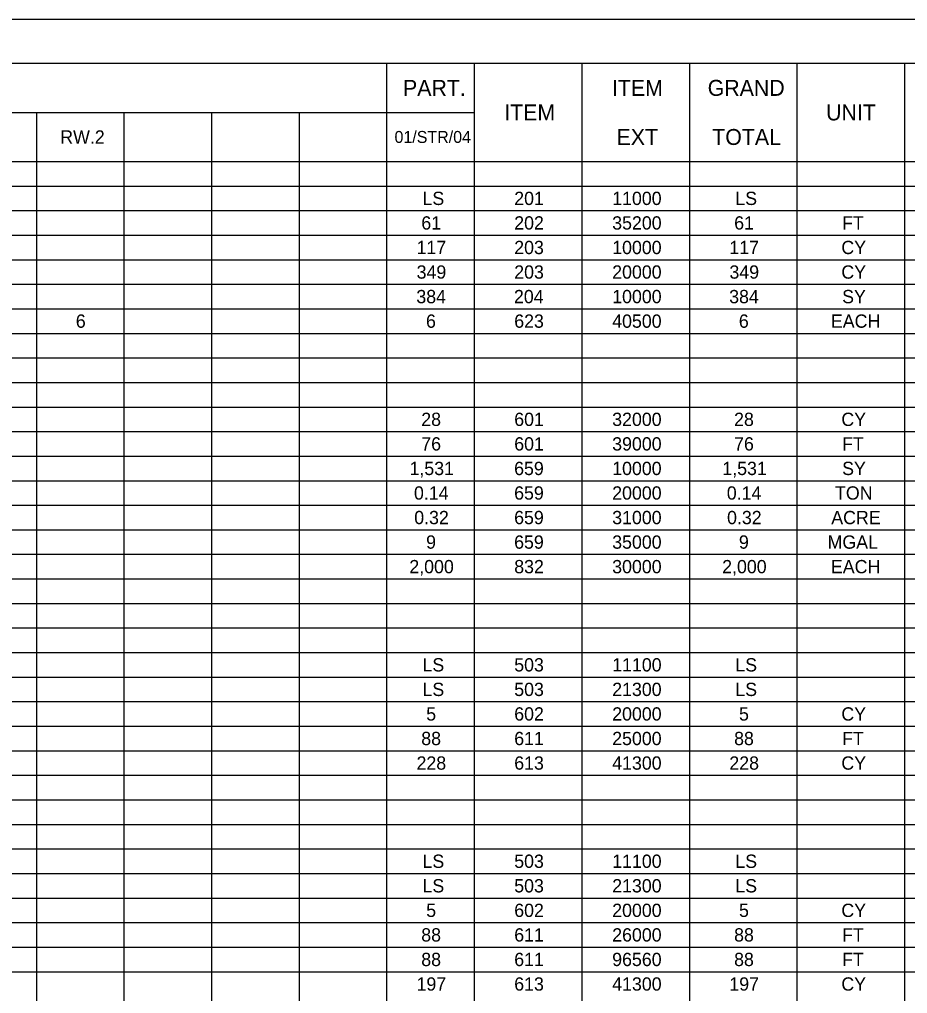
# Model space of a CAD drawing. Extents: x 0 to 44.3, y 0 to 22.
# Drawn here: x 10.6 to 20.73, y 10.89 to 22 of the extents above; entities that cross this region are included whole.
import ezdxf

# ---------------------------------------------------------------- set-up
doc = ezdxf.new("R2010")
doc.units = 0
for name, color, linetype in [('SH_Border', 7, 'Continuous'), ('SH_Cut_Line', 7, 'Continuous'), ('SH_Text', 7, 'Continuous')]:
    doc.layers.add(name, color=color, linetype=linetype)

msp = doc.modelspace()

# ---------------------------------------------------------------- linework, layer by layer
at = {"layer": 'SH_Border'}
msp.add_lwpolyline([(1.5, 21.5), (33.5, 21.5), (33.5, 0.5), (1.5, 0.5)], close=True, dxfattribs=at)
at = {"layer": 'SH_Cut_Line'}
msp.add_lwpolyline([(0, 0), (34, 0), (34, 22), (0, 22)], close=True, dxfattribs=at)
at = {"layer": 'SH_Text'}
for p, q in [((1.5, 21.5), (32, 21.5)), ((14.786, 21.5), (14.786, 0.5)), ((15.785, 21.5), (15.785, 0.5)), ((17.012, 21.5), (17.012, 0.5)), ((18.239, 21.5), (18.239, 0.5)), ((19.466, 21.5), (19.466, 0.5)), ((20.693, 21.5), (20.693, 0.5)), ((1.5, 20.94), (15.785, 20.94)), ((10.794, 20.94), (10.794, 0.5)), ((11.792, 20.94), (11.792, 0.5)), ((12.79, 20.94), (12.79, 0.5)), ((13.788, 20.94), (13.788, 0.5)), ((1.5, 20.38), (32, 20.38)), ((1.5, 20.1), (32, 20.1)), ((1.5, 19.82), (32, 19.82)), ((1.5, 19.54), (32, 19.54)), ((1.5, 19.26), (32, 19.26)), ((1.5, 18.98), (32, 18.98)), ((1.5, 18.7), (32, 18.7)), ((1.5, 18.42), (32, 18.42)), ((1.5, 18.14), (32, 18.14)), ((1.5, 17.86), (32, 17.86)), ((1.5, 17.58), (32, 17.58)), ((1.5, 17.3), (32, 17.3)), ((1.5, 17.02), (32, 17.02)), ((1.5, 16.74), (32, 16.74)), ((1.5, 16.46), (32, 16.46)), ((1.5, 16.18), (32, 16.18)), ((1.5, 15.9), (32, 15.9)), ((1.5, 15.62), (32, 15.62)), ((1.5, 15.34), (32, 15.34)), ((1.5, 15.06), (32, 15.06)), ((1.5, 14.78), (32, 14.78)), ((1.5, 14.5), (32, 14.5)), ((1.5, 14.22), (32, 14.22)), ((1.5, 13.94), (32, 13.94)), ((1.5, 13.66), (32, 13.66)), ((1.5, 13.38), (32, 13.38)), ((1.5, 13.1), (32, 13.1)), ((1.5, 12.82), (32, 12.82)), ((1.5, 12.54), (32, 12.54)), ((1.5, 12.26), (32, 12.26)), ((1.5, 11.98), (32, 11.98)), ((1.5, 11.7), (32, 11.7)), ((1.5, 11.42), (32, 11.42)), ((1.5, 11.14), (32, 11.14))]:
    msp.add_line(p, q, dxfattribs=at)

# ---------------------------------------------------------------- texts
for s, height, p in [('PART.', 0.1818, (14.974, 21.129)), ('ITEM', 0.1818, (17.356, 21.129)), ('GRAND', 0.1818, (18.448, 21.129)), ('ITEM', 0.1818, (16.128, 20.849)), ('UNIT', 0.1818, (19.798, 20.849)), ('RW.2', 0.1515, (11.066, 20.584)), ('01/STR/04', 0.1364, (14.877, 20.592)), ('EXT', 0.1818, (17.409, 20.569)), ('TOTAL', 0.1818, (18.5, 20.569)), ('LS', 0.1515, (15.196, 19.884)), ('201', 0.1515, (16.242, 19.884)), ('11000', 0.1515, (17.359, 19.884)), ('LS', 0.1515, (18.763, 19.884)), ('61', 0.1515, (15.183, 19.604)), ('202', 0.1515, (16.242, 19.604)), ('35200', 0.1515, (17.359, 19.604)), ('61', 0.1515, (18.75, 19.604)), ('FT', 0.1515, (19.98, 19.604)), ('117', 0.1515, (15.128, 19.324)), ('203', 0.1515, (16.242, 19.324)), ('10000', 0.1515, (17.359, 19.324)), ('117', 0.1515, (18.695, 19.324)), ('CY', 0.1515, (19.972, 19.324)), ('349', 0.1515, (15.129, 19.044)), ('203', 0.1515, (16.242, 19.044)), ('20000', 0.1515, (17.359, 19.044)), ('349', 0.1515, (18.696, 19.044)), ('CY', 0.1515, (19.972, 19.044)), ('384', 0.1515, (15.126, 18.764)), ('204', 0.1515, (16.239, 18.764)), ('10000', 0.1515, (17.359, 18.764)), ('384', 0.1515, (18.693, 18.764)), ('SY', 0.1515, (19.981, 18.764)), ('6', 0.152, (11.243, 18.484)), ('6', 0.152, (15.236, 18.484)), ('623', 0.1515, (16.242, 18.484)), ('40500', 0.1515, (17.359, 18.484)), ('6', 0.152, (18.803, 18.484)), ('EACH', 0.1515, (19.853, 18.484)), ('28', 0.1515, (15.182, 17.364)), ('601', 0.1515, (16.242, 17.364)), ('32000', 0.1515, (17.359, 17.364)), ('28', 0.1515, (18.749, 17.364)), ('CY', 0.1515, (19.972, 17.364)), ('76', 0.1515, (15.182, 17.084)), ('601', 0.1515, (16.242, 17.084)), ('39000', 0.1515, (17.359, 17.084)), ('76', 0.1515, (18.749, 17.084)), ('FT', 0.1515, (19.98, 17.084)), ('1,531', 0.1515, (15.048, 16.804)), ('659', 0.1515, (16.241, 16.804)), ('10000', 0.1515, (17.359, 16.804)), ('1,531', 0.1515, (18.615, 16.804)), ('SY', 0.1515, (19.981, 16.804)), ('0.14', 0.1515, (15.099, 16.524)), ('659', 0.1515, (16.241, 16.524)), ('20000', 0.1515, (17.359, 16.524)), ('0.14', 0.1515, (18.666, 16.524)), ('TON', 0.1515, (19.9, 16.524)), ('0.32', 0.1515, (15.102, 16.244)), ('659', 0.1515, (16.241, 16.244)), ('31000', 0.1515, (17.359, 16.244)), ('0.32', 0.1515, (18.669, 16.244)), ('ACRE', 0.1515, (19.857, 16.244)), ('9', 0.152, (15.237, 15.964)), ('659', 0.1515, (16.241, 15.964)), ('35000', 0.1515, (17.359, 15.964)), ('9', 0.152, (18.804, 15.964)), ('MGAL', 0.1515, (19.815, 15.964)), ('2,000', 0.1515, (15.046, 15.684)), ('832', 0.1515, (16.242, 15.684)), ('30000', 0.1515, (17.359, 15.684)), ('2,000', 0.1515, (18.613, 15.684)), ('EACH', 0.1515, (19.853, 15.684)), ('LS', 0.1515, (15.196, 14.564)), ('503', 0.1515, (16.242, 14.564)), ('11100', 0.1515, (17.359, 14.564)), ('LS', 0.1515, (18.763, 14.564)), ('LS', 0.1515, (15.196, 14.284)), ('503', 0.1515, (16.242, 14.284)), ('21300', 0.1515, (17.359, 14.284)), ('LS', 0.1515, (18.763, 14.284)), ('5', 0.152, (15.238, 14.004)), ('602', 0.1515, (16.242, 14.004)), ('20000', 0.1515, (17.359, 14.004)), ('5', 0.152, (18.805, 14.004)), ('CY', 0.1515, (19.972, 14.004)), ('88', 0.1515, (15.182, 13.724)), ('611', 0.1515, (16.242, 13.724)), ('25000', 0.1515, (17.359, 13.724)), ('88', 0.1515, (18.749, 13.724)), ('FT', 0.1515, (19.98, 13.724)), ('228', 0.1515, (15.128, 13.444)), ('613', 0.1515, (16.242, 13.444)), ('41300', 0.1515, (17.359, 13.444)), ('228', 0.1515, (18.695, 13.444)), ('CY', 0.1515, (19.972, 13.444)), ('LS', 0.1515, (15.196, 12.324)), ('503', 0.1515, (16.242, 12.324)), ('11100', 0.1515, (17.359, 12.324)), ('LS', 0.1515, (18.763, 12.324)), ('LS', 0.1515, (15.196, 12.044)), ('503', 0.1515, (16.242, 12.044)), ('21300', 0.1515, (17.359, 12.044)), ('LS', 0.1515, (18.763, 12.044)), ('5', 0.152, (15.238, 11.764)), ('602', 0.1515, (16.242, 11.764)), ('20000', 0.1515, (17.359, 11.764)), ('5', 0.152, (18.805, 11.764)), ('CY', 0.1515, (19.972, 11.764)), ('88', 0.1515, (15.182, 11.484)), ('611', 0.1515, (16.242, 11.484)), ('26000', 0.1515, (17.359, 11.484)), ('88', 0.1515, (18.749, 11.484)), ('FT', 0.1515, (19.98, 11.484)), ('88', 0.1515, (15.182, 11.204)), ('611', 0.1515, (16.242, 11.204)), ('96560', 0.1515, (17.359, 11.204)), ('88', 0.1515, (18.749, 11.204)), ('FT', 0.1515, (19.98, 11.204)), ('197', 0.1515, (15.128, 10.924)), ('613', 0.1515, (16.242, 10.924)), ('41300', 0.1515, (17.359, 10.924)), ('197', 0.1515, (18.695, 10.924)), ('CY', 0.1515, (19.972, 10.924))]:
    msp.add_text(s, height=height, dxfattribs=at).set_placement(p)

doc.saveas('drawing.dxf')
